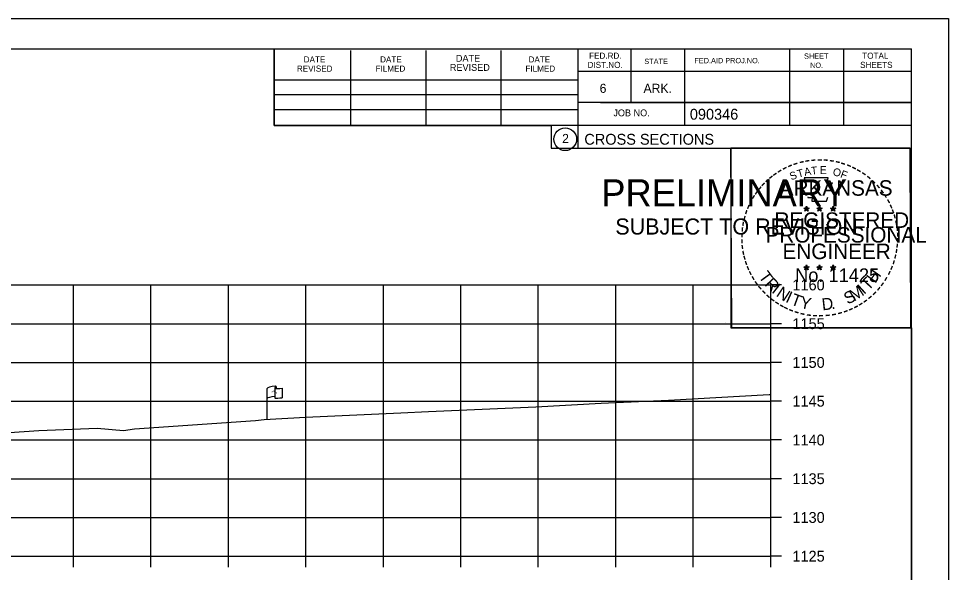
# Model space of a CAD drawing. Extents: x 1368971 to 1374497, y 378717 to 381839.
# Drawn here: x 1369685.8 to 1369805.9, y 379217.1 to 379288.5 of the extents above; entities that cross this region are included whole.
import ezdxf

# ---------------------------------------------------------------- set-up
doc = ezdxf.new("R2010")
doc.units = 0
for name, color, linetype in [('E_Existing ROW', 7, 'Continuous'), ('R_Axis', 7, 'Continuous'), ('R_Axis Annot', 7, 'Continuous'), ('R_Border', 7, 'Continuous'), ('R_Border PE', 7, 'Continuous'), ('R_Border Prem', 7, 'Continuous'), ('R_Exist Surface', 7, 'Continuous'), ('R_Grid', 7, 'Continuous'), ('R_No Plot', 7, 'Continuous')]:
    doc.layers.add(name, color=color, linetype=linetype)

msp = doc.modelspace()

# ---------------------------------------------------------------- linework, layer by layer
at = {"layer": 'E_Existing ROW'}
for p, q in [((1369717.93, 379236.81), (1369717.93, 379240.76)), ((1369718.93, 379240.85), (1369718.93, 379240.84)), ((1369718.93, 379240.84), (1369718.93, 379239.61)), ((1369719.09, 379241.01), (1369719.09, 379240.77)), ((1369719.86, 379240.81), (1369719.86, 379239.57))]:
    msp.add_line(p, q, dxfattribs=at)
for centre, radius, start, end in [((1369719, 379240.85), 0.078, 88.6458, 274.2828), ((1369719.01, 379241.01), 0.0783, 263.0712, 93.9564), ((1369719, 379239.61), 0.0783, 180, 273.9564)]:
    msp.add_arc(centre, radius, start, end, dxfattribs=at)
for centre, major_axis, ratio, start_param, end_param in [((1369719.51, 379240.8), (-1.58, -0.04), 0.19887, 5.030368, 6.283185), ((1369720.22, 379240.92), (-1.23, -0.13), 0.052933, 0.159456, 1.268315), ((1369719.51, 379239.48), (-1.58, -0.04), 0.19887, 5.083035, 6.194897), ((1369720.22, 379239.68), (-1.23, -0.13), 0.052933, 0.159456, 1.268315)]:
    msp.add_ellipse(centre, major_axis=major_axis, ratio=ratio, start_param=start_param, end_param=end_param, dxfattribs=at)
at = {"layer": 'R_Axis'}
for p, q in [((1369782.93, 379219.14), (1369782.93, 379254.14)), ((1369784.33, 379254.14), (1369782.93, 379254.14)), ((1369784.33, 379249.14), (1369782.93, 379249.14)), ((1369784.33, 379244.14), (1369782.93, 379244.14)), ((1369784.33, 379239.14), (1369782.93, 379239.14)), ((1369784.33, 379234.14), (1369782.93, 379234.14)), ((1369784.33, 379229.14), (1369782.93, 379229.14)), ((1369784.33, 379224.14), (1369782.93, 379224.14)), ((1369502.93, 379219.14), (1369782.93, 379219.14)), ((1369692.93, 379217.74), (1369692.93, 379219.14)), ((1369702.93, 379217.74), (1369702.93, 379219.14)), ((1369712.93, 379217.74), (1369712.93, 379219.14)), ((1369722.93, 379217.74), (1369722.93, 379219.14)), ((1369732.93, 379217.74), (1369732.93, 379219.14)), ((1369742.93, 379217.74), (1369742.93, 379219.14)), ((1369752.93, 379217.74), (1369752.93, 379219.14)), ((1369762.93, 379217.74), (1369762.93, 379219.14)), ((1369772.93, 379217.74), (1369772.93, 379219.14)), ((1369782.93, 379217.74), (1369782.93, 379219.14)), ((1369784.33, 379219.14), (1369782.93, 379219.14))]:
    msp.add_line(p, q, dxfattribs=at)
at = {"layer": 'R_Border'}
for p, q in [((1369484.93, 379284.6), (1369801.11, 379284.6)), ((1369718.85, 379274.72), (1369718.85, 379284.6)), ((1369728.71, 379274.72), (1369728.71, 379284.4)), ((1369738.47, 379274.72), (1369738.47, 379284.4)), ((1369748.15, 379274.72), (1369748.15, 379284.4)), ((1369758.01, 379284.6), (1369758.01, 379271.8)), ((1369764.85, 379284.6), (1369764.85, 379277.66)), ((1369771.79, 379284.6), (1369771.79, 379274.72)), ((1369785.37, 379284.6), (1369785.37, 379274.72)), ((1369792.31, 379284.6), (1369792.31, 379274.72)), ((1369801.11, 379079.14), (1369801.11, 379284.6)), ((1369801.11, 379281.66), (1369758.01, 379281.66)), ((1369801.11, 379281.68), (1369801.11, 379281.68)), ((1369718.85, 379280.58), (1369758.01, 379280.58)), ((1369718.85, 379278.72), (1369758.01, 379278.72)), ((1369801.11, 379277.66), (1369758.01, 379277.66)), ((1369760.97, 379277.66), (1369801.11, 379277.66)), ((1369718.85, 379274.72), (1369718.85, 379276.78)), ((1369718.85, 379276.78), (1369758.01, 379276.78)), ((1369801.11, 379274.72), (1369718.85, 379274.72)), ((1369758.01, 379271.8), (1369801.11, 379271.8))]:
    msp.add_line(p, q, dxfattribs=at)
msp.add_circle((1369756.4, 379272.94), 1.47, dxfattribs=at)
at = {"layer": 'R_Border PE'}
for p, q in [((1369787.19, 379264.06), (1369787.54, 379263.95)), ((1369787.19, 379264.06), (1369787.45, 379264.01)), ((1369787.19, 379264.06), (1369787.43, 379263.94)), ((1369787.33, 379263.65), (1369787.54, 379263.95)), ((1369787.54, 379264.31), (1369787.5, 379264.06)), ((1369787.54, 379263.95), (1369787.54, 379264.31)), ((1369787.54, 379264.31), (1369787.59, 379264.06)), ((1369787.89, 379264.06), (1369787.54, 379263.95)), ((1369787.76, 379263.65), (1369787.54, 379263.95)), ((1369787.89, 379264.06), (1369787.6, 379264.01)), ((1369787.76, 379263.65), (1369787.62, 379263.94)), ((1369787.89, 379264.06), (1369787.69, 379263.96)), ((1369788.86, 379264.06), (1369789.21, 379263.95)), ((1369788.86, 379264.06), (1369789.12, 379264.01)), ((1369788.86, 379264.06), (1369789.1, 379263.94)), ((1369789, 379263.65), (1369789.21, 379263.95)), ((1369789.21, 379264.31), (1369789.17, 379264.06)), ((1369789.21, 379263.95), (1369789.21, 379264.31)), ((1369789.21, 379264.31), (1369789.26, 379264.06)), ((1369789.56, 379264.06), (1369789.21, 379263.95)), ((1369789.43, 379263.65), (1369789.21, 379263.95)), ((1369789.56, 379264.06), (1369789.27, 379264.01)), ((1369789.43, 379263.65), (1369789.29, 379263.94)), ((1369789.56, 379264.06), (1369789.36, 379263.96)), ((1369790.63, 379264.05), (1369790.98, 379263.94)), ((1369790.63, 379264.05), (1369790.88, 379264)), ((1369790.63, 379264.05), (1369790.87, 379263.93)), ((1369790.76, 379263.64), (1369790.98, 379263.94)), ((1369790.98, 379264.3), (1369790.94, 379264.05)), ((1369790.98, 379263.94), (1369790.98, 379264.3)), ((1369790.98, 379264.3), (1369791.03, 379264.05)), ((1369791.32, 379264.05), (1369790.98, 379263.94)), ((1369791.19, 379263.64), (1369790.98, 379263.94)), ((1369791.32, 379264.05), (1369791.04, 379264)), ((1369791.19, 379263.64), (1369791.05, 379263.93)), ((1369791.32, 379264.05), (1369791.12, 379263.95)), ((1369787.33, 379263.65), (1369787.45, 379263.9)), ((1369787.33, 379263.65), (1369787.54, 379263.87)), ((1369787.76, 379263.65), (1369787.54, 379263.87)), ((1369789, 379263.65), (1369789.12, 379263.9)), ((1369789, 379263.65), (1369789.21, 379263.87)), ((1369789.43, 379263.65), (1369789.21, 379263.87)), ((1369790.76, 379263.64), (1369790.89, 379263.88)), ((1369790.76, 379263.64), (1369790.98, 379263.86)), ((1369791.19, 379263.64), (1369790.98, 379263.85)), ((1369787.54, 379256.74), (1369787.5, 379256.49)), ((1369787.54, 379256.38), (1369787.54, 379256.74)), ((1369787.54, 379256.74), (1369787.59, 379256.49)), ((1369789.21, 379256.74), (1369789.17, 379256.49)), ((1369789.21, 379256.38), (1369789.21, 379256.74)), ((1369789.21, 379256.74), (1369789.26, 379256.49)), ((1369790.98, 379256.73), (1369790.93, 379256.48)), ((1369790.98, 379256.37), (1369790.98, 379256.73)), ((1369790.98, 379256.73), (1369791.02, 379256.48)), ((1369787.19, 379256.49), (1369787.54, 379256.38)), ((1369787.19, 379256.49), (1369787.44, 379256.44)), ((1369787.19, 379256.49), (1369787.43, 379256.36)), ((1369787.32, 379256.08), (1369787.54, 379256.38)), ((1369787.32, 379256.08), (1369787.45, 379256.32)), ((1369787.32, 379256.08), (1369787.54, 379256.3)), ((1369787.89, 379256.49), (1369787.54, 379256.38)), ((1369787.75, 379256.08), (1369787.54, 379256.38)), ((1369787.75, 379256.08), (1369787.54, 379256.29)), ((1369787.89, 379256.49), (1369787.6, 379256.44)), ((1369787.75, 379256.08), (1369787.62, 379256.37)), ((1369787.89, 379256.49), (1369787.68, 379256.38)), ((1369788.86, 379256.49), (1369789.21, 379256.38)), ((1369788.86, 379256.49), (1369789.11, 379256.44)), ((1369788.86, 379256.49), (1369789.1, 379256.36)), ((1369788.99, 379256.08), (1369789.21, 379256.38)), ((1369788.99, 379256.08), (1369789.12, 379256.32)), ((1369788.99, 379256.08), (1369789.21, 379256.3)), ((1369789.56, 379256.49), (1369789.21, 379256.38)), ((1369789.42, 379256.08), (1369789.21, 379256.38)), ((1369789.42, 379256.08), (1369789.21, 379256.29)), ((1369789.56, 379256.49), (1369789.27, 379256.44)), ((1369789.42, 379256.08), (1369789.28, 379256.37)), ((1369789.56, 379256.49), (1369789.35, 379256.38)), ((1369790.63, 379256.48), (1369790.98, 379256.37)), ((1369790.63, 379256.48), (1369790.88, 379256.43)), ((1369790.63, 379256.48), (1369790.86, 379256.35)), ((1369790.76, 379256.07), (1369790.98, 379256.37)), ((1369790.76, 379256.07), (1369790.89, 379256.31)), ((1369790.76, 379256.07), (1369790.97, 379256.29)), ((1369791.19, 379256.07), (1369790.97, 379256.28)), ((1369791.32, 379256.48), (1369790.98, 379256.37)), ((1369791.19, 379256.07), (1369790.98, 379256.37)), ((1369791.32, 379256.48), (1369791.04, 379256.43)), ((1369791.19, 379256.07), (1369791.05, 379256.36)), ((1369791.32, 379256.48), (1369791.12, 379256.37))]:
    msp.add_line(p, q, dxfattribs=at)
for points in [[(1369787.24, 379267.94), (1369787.5, 379267.11)], [(1369790.75, 379267.02), (1369790.89, 379267.3), (1369790.2, 379267.28), (1369790.35, 379267.94), (1369787.24, 379267.94)], [(1369787.73, 379265.51), (1369787.73, 379265.43), (1369788.29, 379265.41), (1369788.24, 379264.94), (1369790.11, 379264.94), (1369790.31, 379265.47)], [(1369787.54, 379264.31), (1369787.76, 379263.65), (1369787.19, 379264.06), (1369787.89, 379264.06), (1369787.33, 379263.65), (1369787.54, 379264.31)], [(1369789.21, 379264.31), (1369789.43, 379263.65), (1369788.86, 379264.06), (1369789.56, 379264.06), (1369789, 379263.65), (1369789.21, 379264.31)], [(1369790.98, 379264.3), (1369791.19, 379263.64), (1369790.63, 379264.05), (1369791.32, 379264.05), (1369790.76, 379263.64), (1369790.98, 379264.3)], [(1369787.54, 379256.74), (1369787.75, 379256.08), (1369787.19, 379256.49), (1369787.89, 379256.49), (1369787.32, 379256.08), (1369787.54, 379256.74)], [(1369789.21, 379256.74), (1369789.42, 379256.08), (1369788.86, 379256.49), (1369789.56, 379256.49), (1369788.99, 379256.08), (1369789.21, 379256.74)], [(1369790.98, 379256.73), (1369791.19, 379256.07), (1369790.63, 379256.48), (1369791.32, 379256.48), (1369790.76, 379256.07), (1369790.98, 379256.73)]]:
    msp.add_lwpolyline(points, dxfattribs=at)
for centre, radius in [((1369787.54, 379263.95), 0.172), ((1369787.54, 379263.95), 0.145), ((1369787.54, 379263.95), 0.116), ((1369787.54, 379263.95), 0.0991), ((1369787.54, 379263.95), 0.0747), ((1369787.54, 379263.95), 0.0495), ((1369787.54, 379263.95), 0.0296), ((1369789.21, 379263.95), 0.172), ((1369789.21, 379263.95), 0.145), ((1369789.21, 379263.95), 0.116), ((1369789.21, 379263.95), 0.0991), ((1369789.21, 379263.95), 0.0747), ((1369789.21, 379263.95), 0.0495), ((1369789.21, 379263.95), 0.0296), ((1369790.98, 379263.94), 0.172), ((1369790.98, 379263.94), 0.145), ((1369790.98, 379263.94), 0.116), ((1369790.98, 379263.94), 0.0991), ((1369790.98, 379263.94), 0.0747), ((1369790.98, 379263.94), 0.0495), ((1369790.98, 379263.94), 0.0296), ((1369787.54, 379256.37), 0.172), ((1369787.54, 379256.37), 0.145), ((1369787.54, 379256.37), 0.116), ((1369787.54, 379256.37), 0.0991), ((1369787.54, 379256.37), 0.0747), ((1369787.54, 379256.37), 0.0495), ((1369787.54, 379256.37), 0.0296), ((1369789.21, 379256.37), 0.172), ((1369789.21, 379256.37), 0.145), ((1369789.21, 379256.37), 0.116), ((1369789.21, 379256.37), 0.0991), ((1369789.21, 379256.37), 0.0747), ((1369789.21, 379256.37), 0.0495), ((1369789.21, 379256.37), 0.0296), ((1369790.97, 379256.36), 0.172), ((1369790.97, 379256.36), 0.145), ((1369790.97, 379256.36), 0.116), ((1369790.97, 379256.36), 0.0991), ((1369790.97, 379256.36), 0.0747), ((1369790.97, 379256.36), 0.0495), ((1369790.97, 379256.36), 0.0296)]:
    msp.add_circle(centre, radius, dxfattribs=at)
at = {"layer": 'R_Exist Surface'}
msp.add_lwpolyline([(1369671.4, 379234.19), (1369688.45, 379235.37), (1369695.98, 379235.68), (1369699.38, 379235.37), (1369700.8, 379235.57), (1369716.41, 379236.65), (1369717.53, 379236.78), (1369722.87, 379237.09), (1369735.19, 379237.62), (1369738.77, 379237.8), (1369752.61, 379238.42), (1369761.04, 379238.87), (1369769.75, 379239.28), (1369782.73, 379239.99), (1369782.93, 379240)], dxfattribs=at)
at = {"layer": 'R_Grid'}
for p, q in [((1369502.93, 379254.14), (1369782.93, 379254.14)), ((1369692.93, 379219.14), (1369692.93, 379254.14)), ((1369702.93, 379219.14), (1369702.93, 379254.14)), ((1369712.93, 379219.14), (1369712.93, 379254.14)), ((1369722.93, 379219.14), (1369722.93, 379254.14)), ((1369732.93, 379219.14), (1369732.93, 379254.14)), ((1369742.93, 379219.14), (1369742.93, 379254.14)), ((1369752.93, 379219.14), (1369752.93, 379254.14)), ((1369762.93, 379219.14), (1369762.93, 379254.14)), ((1369772.93, 379219.14), (1369772.93, 379254.14)), ((1369782.93, 379219.14), (1369782.93, 379254.14)), ((1369502.93, 379249.14), (1369782.93, 379249.14)), ((1369502.93, 379244.14), (1369782.93, 379244.14)), ((1369502.93, 379239.14), (1369782.93, 379239.14)), ((1369502.93, 379234.14), (1369782.93, 379234.14)), ((1369502.93, 379229.14), (1369782.93, 379229.14)), ((1369502.93, 379224.14), (1369782.93, 379224.14)), ((1369502.93, 379219.14), (1369782.93, 379219.14))]:
    msp.add_line(p, q, dxfattribs=at)
at = {"layer": 'R_No Plot'}
for p, q in [((1369472.53, 379288.5), (1369805.86, 379288.5)), ((1369777.14, 379249.35), (1369777.14, 379249.35))]:
    msp.add_line(p, q, dxfattribs=at)
for points in [[(1369472.52, 379288.5), (1369805.86, 379288.5), (1369805.86, 379075.16), (1369472.52, 379075.16)], [(1369718.85, 379284.6), (1369718.85, 379274.72), (1369754.58, 379274.72), (1369754.58, 379271.8), (1369777.78, 379271.8), (1369777.78, 379248.59), (1369801.11, 379248.59), (1369801.11, 379079.14), (1369484.93, 379079.14), (1369484.93, 379284.6)], [(1369777.78, 379271.84), (1369800.88, 379271.84), (1369800.99, 379248.59), (1369777.9, 379248.59)]]:
    msp.add_lwpolyline(points, close=True, dxfattribs=at)

# ---------------------------------------------------------------- texts
at = {"layer": 'E_Existing ROW'}
for s, height, rotation, p in [('R ', 0.2, 9.9884, (1369718.45, 379240.26)), (' O', 0.2, 9.9884, (1369718.59, 379240.3)), ('W', 0.2, 351.1788, (1369718.92, 379240.14)), ('DWB 11-9-07', 0.001, 90, (1369719.09, 379240.77)), ('DWB 11-9-07', 0.001, 5.0717, (1369719.85, 379239.57)), ('DWB 11-9-07', 0.001, 90, (1369717.93, 379236.81))]:
    msp.add_text(s, height=height, rotation=rotation, dxfattribs=at).set_placement(p)
at = {"layer": 'R_Axis Annot'}
for s, p in [('1160', (1369785.73, 379253.44)), ('1155', (1369785.73, 379248.44)), ('1150', (1369785.73, 379243.44)), ('1145', (1369785.73, 379238.44)), ('1140', (1369785.73, 379233.44)), ('1135', (1369785.73, 379228.44)), ('1130', (1369785.73, 379223.44)), ('1125', (1369785.73, 379218.44))]:
    msp.add_text(s, height=1.4, dxfattribs=at).set_placement(p)
at = {"layer": 'R_Border'}
for s, height, p in [('DATE', 0.782, (1369722.65, 379282.84)), ('DATE', 0.782, (1369732.51, 379282.84)), ('DATE', 0.879, (1369742.29, 379282.94)), ('DATE', 0.782, (1369751.67, 379282.84)), ('FED.RD.', 0.782, (1369759.49, 379283.32)), ('STATE', 0.684, (1369766.61, 379282.64)), ('FED.AID PROJ.NO.', 0.684, (1369773.07, 379282.74)), ('SHEET', 0.684, (1369787.23, 379283.32)), ('TOTAL', 0.782, (1369794.75, 379283.32)), ('REVISED', 0.782, (1369721.77, 379281.66)), ('FILMED', 0.782, (1369731.93, 379281.66)), ('REVISED', 0.879, (1369741.51, 379281.76)), ('FILMED', 0.782, (1369751.27, 379281.66)), ('DIST.NO.', 0.782, (1369759.29, 379282.14)), ('NO.', 0.684, (1369788.01, 379282.14)), ('SHEETS', 0.782, (1369794.47, 379282.14)), ('6', 1.17, (1369760.85, 379278.92)), ('ARK.', 1.172, (1369766.51, 379278.92)), ('JOB NO.', 0.879, (1369762.61, 379275.9)), ('2', 1.17, (1369756.01, 379272.45)), ('CROSS SECTIONS', 1.4, (1369758.87, 379272.23))]:
    msp.add_text(s, height=height, dxfattribs=at).set_placement(p)
msp.add_text('090346', height=1.4, rotation=360, dxfattribs=at).set_placement((1369772.49, 379275.46))
at = {"layer": 'R_Border PE'}
for s, height, rotation, p in [('-', 1.6, 19.1761, (1369785.98, 379269.06)), ('-', 1.6, 13.6301, (1369786.73, 379269.31)), ('-', 1.6, 10.2193, (1369787.41, 379269.47)), ('-', 1.6, 5.8968, (1369788.14, 379269.58)), ('-', 1.6, 0.1862, (1369788.91, 379269.65)), ('-', 1.6, 357.743, (1369789.64, 379269.64)), ('-', 1.6, 352.1617, (1369790.38, 379269.58)), ('-', 1.6, 347.2049, (1369791.1, 379269.47)), ('-', 1.6, 342.3362, (1369791.73, 379269.31)), ('-', 1.6, 34.0636, (1369784.12, 379268.11)), ('-', 1.6, 28.7918, (1369784.72, 379268.48)), ('-', 1.6, 24.3072, (1369785.35, 379268.8)), ('S', 1, 21.594, (1369785.59, 379267.62)), ('T', 1, 16.4036, (1369786.5, 379267.95)), ('A', 1, 11.2132, (1369787.33, 379268.2)), ('T', 1, 6.0228, (1369788.18, 379268.36)), ('E', 1, 0.8323, (1369789.28, 379268.47)), ('O', 1, 350.4515, (1369790.89, 379268.26)), ('F', 1, 340.0707, (1369791.84, 379268.04)), ('-', 1.6, 337.8551, (1369792.47, 379269.09)), ('-', 1.6, 334.1211, (1369793.1, 379268.82)), ('-', 1.6, 329.6409, (1369793.68, 379268.53)), ('-', 1.6, 42.9622, (1369782.63, 379266.92)), ('-', 1.6, 38.9507, (1369783.07, 379267.34)), ('-', 1.6, 36.2317, (1369783.54, 379267.71)), ('-', 1.6, 325.8627, (1369794.32, 379268.17)), ('-', 1.6, 320.5297, (1369794.93, 379267.75)), ('-', 1.6, 315.5786, (1369795.53, 379267.26)), ('-', 1.6, 50.6142, (1369781.78, 379265.95)), ('-', 1.6, 48.423, (1369782.18, 379266.44)), ('-', 1.6, 309.8797, (1369796.1, 379266.71)), ('-', 1.6, 306.6522, (1369796.62, 379266.11)), ('-', 1.6, 58.0706, (1369781.04, 379264.86)), ('-', 1.6, 54.2325, (1369781.37, 379265.39)), ('-', 1.4, 303.6753, (1369797.11, 379265.54)), ('-', 1.6, 299.6684, (1369797.43, 379264.93)), ('-', 1.6, 67.7743, (1369780.47, 379263.64)), ('-', 1.6, 62.8713, (1369780.73, 379264.25)), ('-', 1.6, 294.6628, (1369797.75, 379264.32)), ('-', 1.6, 75.461, (1369780.06, 379262.29)), ('-', 1.6, 72.3945, (1369780.25, 379263.01)), ('-', 1.6, 290.5728, (1369798.01, 379263.74)), ('-', 1.6, 285.1233, (1369798.24, 379263.16)), ('-', 1.6, 85.1863, (1369779.85, 379260.89)), ('-', 1.6, 81.2013, (1369779.92, 379261.58)), ('-', 1.6, 280.5493, (1369798.44, 379262.42)), ('-', 1.6, 276.5962, (1369798.61, 379261.65)), ('-', 1.6, 89.0622, (1369779.82, 379260.19)), ('-', 1.6, 274.3301, (1369798.67, 379260.93)), ('-', 1.6, 94.1959, (1369779.86, 379259.46)), ('-', 1.6, 98.9479, (1369779.93, 379258.79)), ('-', 1.6, 263.5172, (1369798.68, 379259.63)), ('-', 1.6, 269.9407, (1369798.7, 379260.3)), ('-', 1.6, 101.7149, (1369780.06, 379258.06)), ('-', 1.6, 255.7626, (1369798.5, 379258.3)), ('-', 1.6, 260.9953, (1369798.61, 379258.98)), ('-', 1.6, 105.4578, (1369780.23, 379257.47)), ('-', 1.6, 109.0874, (1369780.44, 379256.84)), ('-', 1.6, 252.8681, (1369798.32, 379257.58)), ('-', 1.6, 114.0643, (1369780.7, 379256.24)), ('-', 1.6, 115.7288, (1369781, 379255.62)), ('T', 1.54, 306.0406, (1369781.3, 379255.21)), ('H', 1.54, 54.6088, (1369796.42, 379254.25)), ('-', 1.6, 244.6197, (1369797.83, 379256.28)), ('-', 1.6, 247.8887, (1369798.1, 379256.91)), ('-', 1.6, 120.4471, (1369781.36, 379255.04)), ('-', 1.6, 125.8934, (1369781.76, 379254.47)), ('R', 1.54, 314.005, (1369782.06, 379254.17)), ('I', 1.54, 321.9694, (1369782.96, 379253.23)), ('T', 1.54, 46.6444, (1369795.53, 379253.31)), ('-', 1.6, 233.8452, (1369797.04, 379254.87)), ('-', 1.6, 239.0712, (1369797.44, 379255.53)), ('-', 1.6, 130.7181, (1369782.22, 379253.92)), ('-', 1.6, 134.2238, (1369782.74, 379253.38)), ('N', 1.54, 326.5002, (1369783.53, 379252.76)), ('I', 1.54, 335.3603, (1369784.74, 379251.98)), ('S', 1.54, 26.9312, (1369792.85, 379251.58)), ('M', 1.54, 32.6563, (1369793.68, 379251.98)), ('I', 1.54, 42.1136, (1369794.97, 379252.83)), ('-', 1.6, 225.7653, (1369796.13, 379253.74)), ('-', 1.6, 231.2538, (1369796.61, 379254.31)), ('-', 1.6, 138.9338, (1369783.26, 379252.91)), ('-', 1.6, 144.6463, (1369783.82, 379252.51)), ('-', 1.6, 148.0898, (1369784.38, 379252.14)), ('T', 1.54, 339.8912, (1369785.4, 379251.65)), ('Y', 1.54, 347.8556, (1369786.62, 379251.2)), ('D', 1.54, 6.3969, (1369789.6, 379250.85)), ('-', 1.6, 215.7363, (1369795.06, 379252.76)), ('-', 1.6, 221.0851, (1369795.61, 379253.24)), ('-', 1.6, 151.5704, (1369784.96, 379251.81)), ('-', 1.6, 154.6002, (1369785.48, 379251.56)), ('-', 1.6, 158.5612, (1369786.11, 379251.31)), ('-', 1.6, 162.7983, (1369786.79, 379251.1)), ('.', 1.54, 13.7642, (1369790.79, 379250.97)), ('-', 1.6, 200.7184, (1369792.72, 379251.44)), ('-', 1.6, 204.2516, (1369793.34, 379251.71)), ('-', 1.6, 207.3568, (1369793.97, 379252.03)), ('-', 1.6, 212.2491, (1369794.52, 379252.38)), ('-', 1.6, 167.5555, (1369787.51, 379250.93)), ('-', 1.6, 173.1155, (1369788.28, 379250.82)), ('-', 1.6, 176.5183, (1369789.03, 379250.77)), ('-', 1.6, 181.5918, (1369789.77, 379250.79)), ('-', 1.6, 185.8167, (1369790.58, 379250.87)), ('-', 1.6, 191.2858, (1369791.32, 379251)), ('-', 1.6, 195.4743, (1369792.05, 379251.2))]:
    msp.add_text(s, height=height, rotation=rotation, dxfattribs=at).set_placement(p)
for s, height, p in [('ARKANSAS', 2, (1369784.09, 379265.65)), ('DWB', 0.01, (1369787.53, 379263.94)), ('DWB', 0.01, (1369789.2, 379263.94)), ('DWB', 0.01, (1369790.96, 379263.93)), ('REGISTERED', 2, (1369783.41, 379261.5)), ('PROFESSIONAL', 2, (1369782.26, 379259.6)), ('ENGINEER', 2, (1369784.45, 379257.47)), ('No. 11425', 1.757, (1369786.08, 379254.52)), ('DWB', 0.01, (1369787.53, 379256.37)), ('DWB', 0.01, (1369789.2, 379256.37)), ('DWB', 0.01, (1369790.96, 379256.36))]:
    msp.add_text(s, height=height, dxfattribs=at).set_placement(p)
at = {"layer": 'R_Border Prem'}
for s, height, p in [('PRELIMINARY', 3.5, (1369761.06, 379264.27)), ('DWB', 0.01, (1369761.81, 379266.12)), ('SUBJECT TO REVISION', 2.0751, (1369762.87, 379260.64))]:
    msp.add_text(s, height=height, dxfattribs=at).set_placement(p)

doc.saveas('drawing.dxf')
